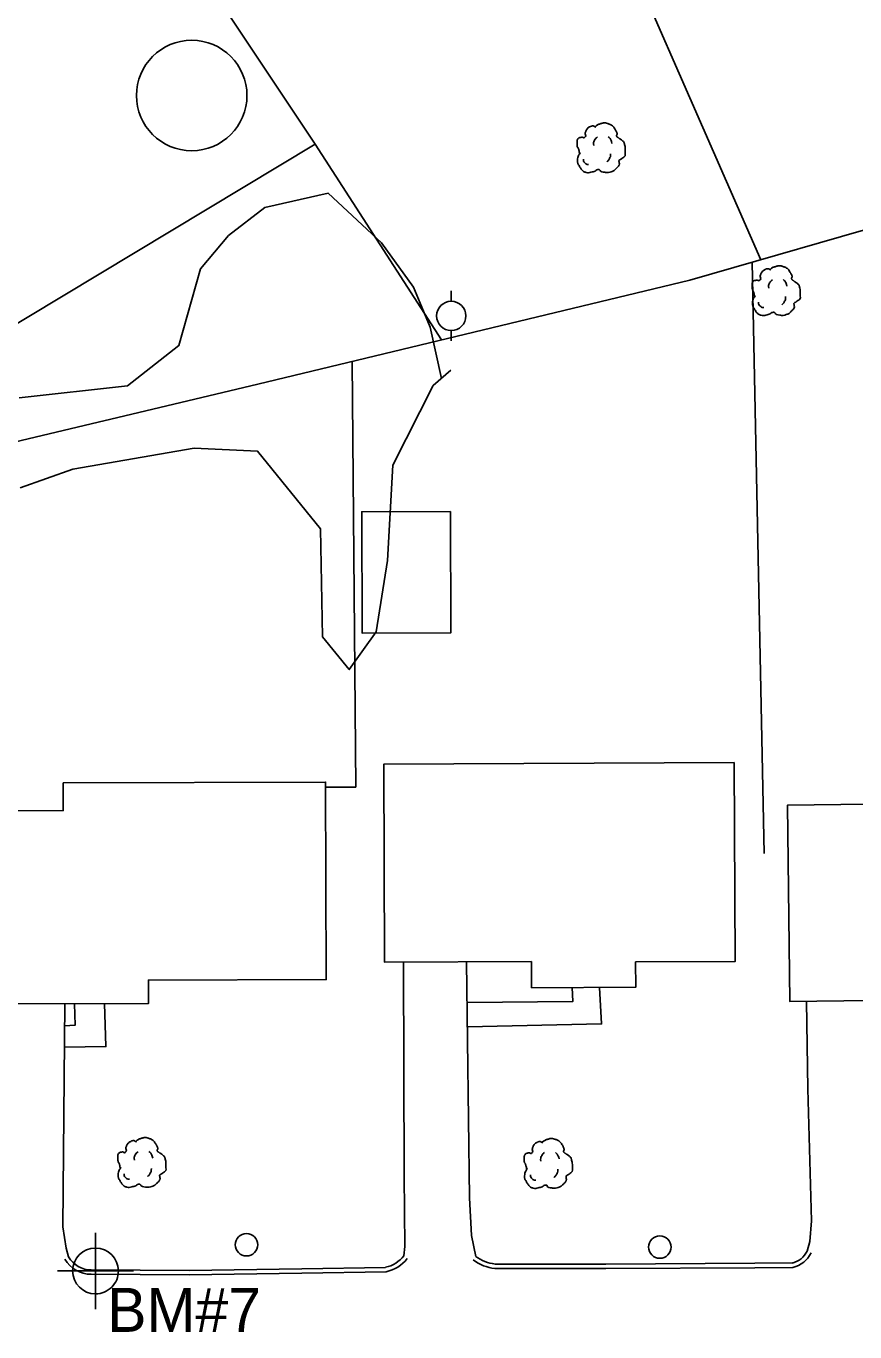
# Model space of a CAD drawing. Extents: x 2145380 to 2156929, y 139568 to 149130.
# Drawn here: x 2149240.8 to 2149353.9, y 143393.4 to 143571.6 of the extents above; entities that cross this region are included whole.
import ezdxf

# ---------------------------------------------------------------- set-up
doc = ezdxf.new("R2010")
doc.units = 0
for name, color, linetype in [('Default', 7, 'Continuous'), ('SURV_Benchmark', 7, 'Continuous'), ('SURV_Text', 7, 'Continuous'), ('TOPO_Asphalt', 7, 'Continuous'), ('TOPO_Building', 7, 'Continuous'), ('TOPO_Concrete', 7, 'Continuous'), ('TOPO_Curb Back', 7, 'Continuous'), ('TOPO_Fence', 7, 'Continuous'), ('TOPO_Power Pole', 7, 'Continuous'), ('TOPO_Sidewalk', 7, 'Continuous'), ('TOPO_Tree', 7, 'Continuous'), ('TOPO_Tree Line', 7, 'Continuous'), ('TOPO_Water Meter', 7, 'Continuous')]:
    doc.layers.add(name, color=color, linetype=linetype)

# ---------------------------------------------------------------- blocks, each defined once
blk = doc.blocks.new('POWPOL')
at = {"layer": 'TOPO_Power Pole'}
for p, q in [((0, 10.16), (0, 17.34)), ((0, -10.16), (0, -17.34))]:
    blk.add_line(p, q, dxfattribs=at)
blk.add_circle((0, 0), 10.16, dxfattribs=at)
blk = doc.blocks.new('TREE')
at = {"layer": 'TOPO_Tree'}
for points in [[(-14.07, -0.4), (-14.17, 0.5), (-14.37, 1.38), (-14.6, 2.25), (-14.84, 3.17), (-15.47, 3.96), (-15.66, 4.9), (-15.8, 5.59), (-15.71, 6.31), (-15.66, 7.01), (-15.6, 7.91), (-15.72, 8.8), (-15.13, 9.66), (-14.62, 10.42), (-13.76, 10.49), (-13.02, 10.72), (-12.18, 10.98), (-11.06, 10), (-10.37, 10.72), (-9.4, 11.74), (-10.29, 13.28), (-9.84, 14.42), (-9.56, 15.15), (-9.32, 15.89), (-8.78, 16.54), (-8.18, 17.26), (-7.5, 17.68), (-6.67, 18.13), (-6.14, 18.41), (-5.61, 18.61), (-5.08, 18.66), (-4.55, 18.71), (-4.02, 18.54), (-3.49, 18.13)], [(-3.49, 17.6), (-3.07, 18.27), (-2.58, 18.8), (-1.9, 19.19), (-1.05, 19.68), (-0.19, 19.96), (0.74, 20.24), (1.62, 20.51), (2.51, 20.82), (3.39, 20.77), (4.1, 20.73), (4.8, 20.47), (5.51, 20.24), (6.43, 19.95), (7.32, 19.73), (8.15, 19.19), (9.36, 18.4), (10.02, 17.21), (10.8, 16.01), (11.24, 15.33), (11.58, 14.62), (11.86, 13.89), (12.17, 13.08), (11.37, 12.02), (11.86, 11.25), (12, 11.03), (12.18, 10.86), (12.39, 10.72), (12.91, 10.35), (13.45, 10.02), (13.97, 9.66), (14.7, 9.16), (15.41, 8.68), (16.09, 8.07), (16.7, 7.53), (16.93, 6.73), (17.15, 5.95), (17.59, 4.38), (17.71, 2.77), (17.68, 1.19), (17.65, -0.25), (17.83, -2.22), (16.62, -3.04), (15.47, -3.83), (14.31, -4.58), (13.16, -5.35)], [(-4.21, 5.09), (-4.46, 6.09), (-4.3, 7.21), (-3.84, 8.21), (-3.33, 9.34), (-2.71, 10.27), (-1.64, 10.97)], [(5.89, 11.15), (6.5, 10.68), (6.96, 10.17), (7.36, 9.5), (7.93, 8.56), (8.31, 7.6), (8.46, 6.56)], [(13.16, -5.34), (13.25, -5.81), (13.36, -6.28), (13.45, -6.75), (13.76, -8.52), (12.24, -10.03), (10.8, -11.51), (9.98, -12.34), (9.13, -12.77), (8.15, -13.1), (5.97, -13.83), (3.32, -13.56), (1.27, -13.1), (0.49, -12.92), (-0.06, -11.44), (-0.84, -11.51), (-2.04, -11.61), (-3.28, -12.78), (-4.55, -13.1), (-6.06, -13.47), (-7.77, -14.03), (-9.31, -13.62), (-11.36, -13.09), (-12.84, -11.41), (-14.07, -9.39), (-15.32, -7.35), (-15.61, -5.13), (-15.13, -3.04), (-14.87, -1.89), (-13.91, -0.75), (-13.54, 0.13)], [(-11.38, -4.46), (-11.47, -5.41), (-11.03, -6.32), (-10.09, -7.22), (-9.3, -7.97), (-8.49, -8.26), (-7.7, -8.14)], [(4.79, -6.29), (5.71, -5.66), (6.3, -4.92), (6.81, -3.91), (7.36, -2.81), (7.63, -1.7), (7.54, -0.6)]]:
    blk.add_open_spline(points, degree=3, dxfattribs=at)
blk = doc.blocks.new('WTRMTR')
at = {"layer": 'Default'}
blk.add_circle((0, 0), 3.89, dxfattribs=at)
blk = doc.blocks.new('BM')
at = {"layer": 'SURV_Benchmark'}
for p, q in [((0, 2.49), (0, 4.15)), ((-2.49, 0), (-4.16, 0)), ((4.16, 0), (2.49, 0)), ((0, -4.16), (0, -2.49))]:
    blk.add_line(p, q, dxfattribs=at)
for points in [[(0, 2.49), (0, 2.49), (0, 0), (2.49, 0), (2.49, 0), (2.49, 0)], [(0, 2.49), (0, 2.49), (0, 0), (2.49, 0), (2.49, 0), (2.49, 0), (2.49, 0)], [(-2.5, 0), (-2.49, 0), (0, 0), (0, -2.49), (0, -2.49)], [(-2.5, 0), (-2.49, 0), (0, 0), (0, -2.49), (0, -2.49)]]:
    blk.add_lwpolyline(points, dxfattribs=at)
for start, end in [(90.0638, 180.0068), (0.0638, 90.0068), (0.0638, 90.0068), (180.0638, 270.0068), (180.0638, 270.0068), (269.9472, 359.9927)]:
    blk.add_arc((0, 0), 2.5, start, end, dxfattribs=at)

msp = doc.modelspace()

# ---------------------------------------------------------------- linework, layer by layer
at = {"layer": 'TOPO_Asphalt'}
for points in [[(2149292.34, 143403.73), (2149292.48, 143405.01), (2149292.38, 143414.68), (2149292.31, 143443.83)], [(2149302.15, 143403.66), (2149301.59, 143406.53), (2149301.32, 143411.68), (2149300.9, 143443.87)], [(2149246.61, 143403.6), (2149246.27, 143404.77), (2149245.84, 143407.7), (2149246.07, 143438.15)], [(2149347.37, 143404.4), (2149347.74, 143405.71), (2149347.97, 143408.51), (2149347.49, 143426.56), (2149347.31, 143438.47)]]:
    msp.add_lwpolyline(points, dxfattribs=at)
at = {"layer": 'TOPO_Building'}
for points in [[(2149298.71, 143505.36), (2149298.76, 143488.79), (2149286.65, 143488.76), (2149286.61, 143505.32)], [(2149337.43, 143471.08), (2149289.6, 143470.85), (2149289.73, 143443.82), (2149309.76, 143443.91), (2149309.78, 143440.33), (2149323.98, 143440.4), (2149323.96, 143443.87), (2149337.56, 143443.93)], [(2149392.13, 143442.92), (2149367.07, 143442.61), (2149367.12, 143438.71), (2149345.03, 143438.44), (2149344.7, 143465.27), (2149355.59, 143465.4), (2149355.54, 143469.3), (2149391.8, 143469.75)], [(2149245.87, 143468.3), (2149281.67, 143468.4), (2149281.75, 143441.45), (2149257.49, 143441.38), (2149257.5, 143438.18), (2149234.94, 143438.12), (2149234.87, 143464.48), (2149245.88, 143464.51)]]:
    msp.add_lwpolyline(points, close=True, dxfattribs=at)
at = {"layer": 'TOPO_Concrete'}
msp.add_circle((2149263.4, 143562.13), 7.54, dxfattribs=at)
at = {"layer": 'TOPO_Curb Back'}
for points in [[(2149249.7, 143401.82), (2149263.06, 143401.75), (2149278.43, 143401.99), (2149289.86, 143402.17)], [(2149304.77, 143402.02), (2149319.92, 143402.02), (2149340.25, 143402.12), (2149345.44, 143402.17)], [(2149304.8, 143402.62), (2149319.91, 143402.62), (2149340.25, 143402.72), (2149345.37, 143402.77)], [(2149249.7, 143401.22), (2149263.07, 143401.15), (2149278.44, 143401.39), (2149289.93, 143401.57)]]:
    msp.add_lwpolyline(points, dxfattribs=at)
for centre, radius, start, end in [((2149249.7, 143405.4), 3.58, 210.0778, 269.9248), ((2149288.91, 143406.45), 4.38, 282.5535, 321.632), ((2149305.33, 143407.88), 5.28, 233.0669, 264.2136), ((2149344.67, 143405.67), 2.99, 283.5236, 334.6904), ((2149344.67, 143405.67), 3.59, 282.3855, 334.6906), ((2149249.7, 143405.4), 4.18, 210.078, 269.909), ((2149288.9, 143406.45), 4.98, 281.8335, 321.6287), ((2149305.33, 143407.88), 5.88, 233.0637, 264.5173)]:
    msp.add_arc(centre, radius, start, end, dxfattribs=at)
at = {"layer": 'TOPO_Fence'}
for p, q in [((2149280.23, 143555.51), (2149297.48, 143528.77)), ((2149339.87, 143539.37), (2149341.5, 143458.66))]:
    msp.add_line(p, q, dxfattribs=at)
for points in [[(2149299.15, 143638.5), (2149296.64, 143637.27), (2149315.52, 143597.99), (2149341.04, 143539.7)], [(2149231.09, 143525.93), (2149280.23, 143555.51), (2149261.78, 143583.24), (2149257.28, 143583.94)], [(2149390.75, 143554.04), (2149331.39, 143536.92), (2149272.41, 143522.75), (2149230.54, 143512.77), (2149229.97, 143514.37), (2149177.38, 143501.54), (2149150.87, 143418.47), (2149134.89, 143422.61), (2149136.76, 143464.68)], [(2149281.67, 143467.71), (2149285.79, 143467.73), (2149285.28, 143525.84)]]:
    msp.add_lwpolyline(points, dxfattribs=at)
at = {"layer": 'TOPO_Sidewalk'}
for points in [[(2149300.97, 143438.31), (2149315.42, 143438.47), (2149315.31, 143440.35)], [(2149301.02, 143435.01), (2149319.33, 143435.4), (2149319.05, 143440.37)], [(2149246.03, 143432.23), (2149251.7, 143432.31), (2149251.5, 143438.17)], [(2149246.05, 143435.16), (2149247.48, 143435.21), (2149247.39, 143438.16)]]:
    msp.add_lwpolyline(points, dxfattribs=at)
at = {"layer": 'TOPO_Tree Line'}
for points in [[(2149297.48, 143523.52), (2149295.96, 143530.5), (2149293.67, 143535.97), (2149289.29, 143542.01), (2149282.01, 143548.8), (2149273.37, 143546.84), (2149268.44, 143543), (2149264.62, 143538.47), (2149261.64, 143528), (2149254.66, 143522.52), (2149239.87, 143520.84)], [(2149240.01, 143508.56), (2149247.16, 143511.14), (2149263.76, 143514), (2149272.38, 143513.57), (2149280.99, 143502.96), (2149281.27, 143488.23), (2149284.9, 143483.77), (2149288.56, 143488.91), (2149290.11, 143498.68), (2149290.85, 143511.69), (2149296.36, 143522.53), (2149298.77, 143524.65)]]:
    msp.add_lwpolyline(points, dxfattribs=at)

# ---------------------------------------------------------------- block references
at = {"layer": 'SURV_Benchmark', "xscale": 1.25, "yscale": 1.25}
msp.add_blockref('BM', (2149250.28, 143401.68), dxfattribs=at)
at = {"layer": 'TOPO_Power Pole', "xscale": 0.19685000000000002, "yscale": 0.19685000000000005}
msp.add_blockref('POWPOL', (2149298.82, 143532.04), dxfattribs=at)
at = {"layer": 'TOPO_Tree', "xscale": 0.19685000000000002, "yscale": 0.19685000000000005}
for p in [(2149319.08, 143554.31), (2149342.96, 143534.81), (2149256.41, 143415.8), (2149311.86, 143415.67)]:
    msp.add_blockref('TREE', p, dxfattribs=at)
at = {"layer": 'TOPO_Water Meter', "xscale": 0.39370000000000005, "yscale": 0.3937000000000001}
for p in [(2149270.88, 143405.26), (2149327.27, 143404.94)]:
    msp.add_blockref('WTRMTR', p, dxfattribs=at)

# ---------------------------------------------------------------- texts
at = {"layer": 'SURV_Text'}
msp.add_text('BM#7', height=6, dxfattribs=at).set_placement((2149251.88, 143393.36))

doc.saveas('drawing.dxf')
